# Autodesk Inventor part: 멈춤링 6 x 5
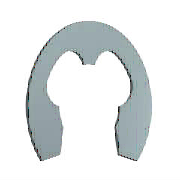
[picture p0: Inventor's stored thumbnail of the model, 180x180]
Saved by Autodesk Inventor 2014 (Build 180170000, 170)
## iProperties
Created: 2012-02
Part Number: 멈춤링 6 x 5
Material: 강철, 연강
Description: 스프링 리테이닝 링
Document SubType Name: Modeling
Standard: JIS B 2805
Designer: mduedu
Standards Organization: JIS
Language: ko-KR
Size Designation: 5
Categories: <MemberInstance><Categories><Category DisplayName="샤프트 부품" InternalName="7f7aeb1f-a693-4053-b835-cee3144e0d98" Mnemonic="SHFT"><Category DisplayName="써클립" Inter
Density: 1 g/cm^3
Appearance: 파란색 - 벽 페인트 - 광택
IsCustomPart: 1
Author: mduedu
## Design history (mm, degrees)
sketch "스케치1"
  geometry: L1 (-0.5, 0.024)-(0, 0.024) reference; L2 (-3.206, 0)-(3.486, 0) reference; L3 (-2.291, -3.976)-(2.291, -3.976); L4 (0, 1.949)-(0, -3.479) reference; L5 (-3, -1.976)-(-2.51, -1.976); L6 (-0.5, 0.024)-(-0.5, 0.509); L7 (0, 2.524)-(2.53, 2.524); L8 (-2.291, -3.976)-(-3.051, -6.131); L9 (0, -0.476)-(-1.278, -0.476); L10 (2.291, -3.976)-(3.051, -6.131); L11 (3, -1.976)-(2.51, -1.976); L12 (0.5, 0.024)-(0.5, 0.509); C1 r 3 at (0, -2.976); A1 r 2.5 centre (0, -2.976) between (-2.368, -2.174) and (-2.291, -3.976); A2 r 0.5 centre (0, 0.024) between (-0.5, 0.024) and (0.5, 0.024); A3 r 5.5 centre (0, -2.976) between (4.351, -6.34) and (-4.351, -6.34); A4 r 4 centre (0, -2.976) between (-1, 0.897) and (-3.529, -1.094); A5 r 0.4 centre (-0.9, 0.509) between (-0.5, 0.509) and (-1, 0.897); A6 r 0.6 centre (-3, -1.376) between (-3.529, -1.094) and (-3, -1.976); A7 r 0.15 centre (-2.51, -2.126) between (-2.368, -2.174) and (-2.51, -1.976); A8 r 0.75 centre (-3.758, -5.881) between (-4.351, -6.34) and (-3.051, -6.131); A9 r 0.75 centre (3.758, -5.881) between (3.051, -6.131) and (4.351, -6.34); A10 r 2.5 centre (0, -2.976) between (2.291, -3.976) and (2.368, -2.174); A11 r 0.15 centre (2.51, -2.126) between (2.51, -1.976) and (2.368, -2.174); A12 r 0.6 centre (3, -1.376) between (3, -1.976) and (3.529, -1.094); A13 r 4 centre (0, -2.976) between (3.529, -1.094) and (1, 0.897); A14 r 0.4 centre (0.9, 0.509) between (1, 0.897) and (0.5, 0.509); 1 further point
  constraints: 30 point on circle, 20 end point, 15 centre point, 13 symmetric about line, 12 tangent, 8 point on line, 4 parallel, 2 coincident, 2 horizontal, 1 concentric, 1 perpendicular, 1 vertical alignment, 9 other
  dimensions: "d0" = 6 diameter of C1 (= WD); "d3" = 1 distance from line of A1.centre L3 (= 0.2 x ND); "d4" = 0.5 radius of A2 (= 0.1 x ND); "d5" = 11 diameter of A3 (= SD2); "d8" = 4 radius of A4 (= 0.8 x ND); "d9" = 1 distance from line of A1.centre L5 (= 0.2 x ND); "d10" = 0.4 radius of A5 (= 0.08 x ND); "d11" = 0.6 radius of A6 (= 0.12 x ND); "d12" = 0.15 radius of A7 (= 0.03 x ND); "d13" = 0.75 radius of A8 (= 0.15 x ND); "d14" = 2.5 distance from line of A1.centre L9 (= 0.5 x ND); "d15" = 2.5 radius of A1 (= 0.5 x ND)
extrude "본체" new body sketch "스케치1" distance "d16" = 0.6 (= SD); taper "d17" = 0 deg
workaxis "Work Axis1"
workaxis "Work Axis2"
workplane "Work Plane1"
body "Solid1"
other parameters: "ND" = 5 [user parameter; used in 14 equation terms], "SD" = 0.6 [user parameter; used in 1 equation term], "WD" = 6 (= WDMIN) [user parameter; used in 1 equation term], "d1" = 8 (= 1.6 x ND), "d2" = 5 (= ND), "SD2" = 11 [user parameter; used in 1 equation term], "d6" = 5 (= ND), "d7" = 0.75 (= 0.15 x ND), "d18" = 0, "d19" = 0, "d27" = 0, "d28" = 0, "WDMIN" = 6 [user parameter; used in 1 equation term], "SNB" = 0.7 [user parameter], "WDMAX" = 8 [user parameter], "BUBRMI" = 1.2 [user parameter]
